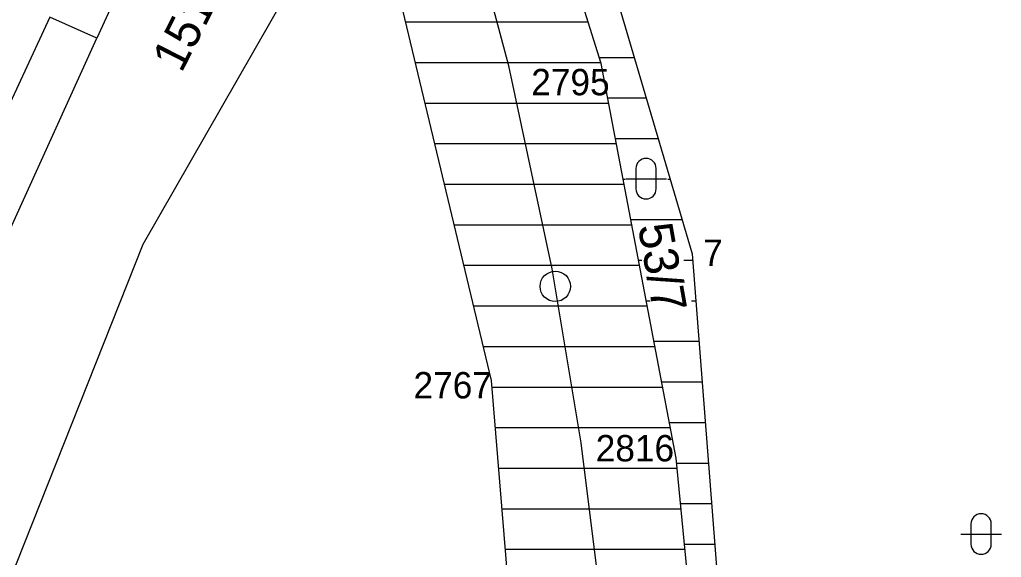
# Model space of a CAD drawing. Extents: x -553916 to -552953, y -1067469 to -1066637.
# Drawn here: x -553532.46 to -553484.03, y -1067025.62 to -1066999.11 of the extents above; entities that cross this region are included whole.
import ezdxf

# ---------------------------------------------------------------- set-up
doc = ezdxf.new("R2010")
doc.units = 0
for name, color, linetype in [('Hranice parcel', 7, 'Continuous'), ('Kolej', 7, 'Continuous'), ('Návěst místo trati', 7, 'Continuous'), ('Parcelní čísla', 7, 'Continuous'), ('Propustek', 7, 'Continuous'), ('Vrstva 1', 7, 'Continuous'), ('Vrstva 60', 7, 'Continuous'), ('Značky kultur', 7, 'Continuous')]:
    doc.layers.add(name, color=color, linetype=linetype)

msp = doc.modelspace()

# ---------------------------------------------------------------- linework, layer by layer
at = {"layer": 'Hranice parcel'}
for p, q in [((-553519.4, -1066979.7), (-553528.66, -1067000.03)), ((-553530.98, -1066998.99), (-553538.9, -1067016.05)), ((-553528.66, -1067000.03), (-553530.98, -1066998.99)), ((-553535.85, -1067015.85), (-553528.66, -1067000.03))]:
    msp.add_line(p, q, dxfattribs=at)
msp.add_lwpolyline([(-553515.43, -1066991.08), (-553526.38, -1067010.19), (-553539.65, -1067043.59), (-553548.33, -1067069.03)], dxfattribs=at)
at = {"layer": 'Kolej'}
msp.add_lwpolyline([(-553503.324, -1067065.808), (-553502.678, -1067054.027), (-553502.762, -1067041.504), (-553503.626, -1067029.057), (-553504.756, -1067019.974), (-553506.183, -1067011.388), (-553508.328, -1067001.388), (-553510.948, -1066991.622), (-553512.921, -1066985.291), (-553515.647, -1066977.347), (-553517.422, -1066972.53), (-553519.157, -1066967.95), (-553522.886, -1066958.375), (-553529.101, -1066942.549), (-553538.686, -1066918.107), (-553542.908, -1066907.329), (-553546.692, -1066897.676), (-553555.025, -1066876.441), (-553564.644, -1066851.894), (-553574.241, -1066827.427), (-553583.19, -1066804.618)], dxfattribs=at)
at = {"layer": 'Návěst místo trati'}
msp.add_circle((-553506.038, -1067012.26), 0.75, dxfattribs=at)
at = {"layer": 'Propustek'}
for p, q in [((-553505.83, -1066988.51), (-553499.28, -1067010.65)), ((-553513.415, -1066999.222), (-553504.415, -1066999.222)), ((-553512.936, -1067001.222), (-553503.788, -1067001.222)), ((-553503.867, -1067000.97), (-553502.144, -1067000.97)), ((-553512.457, -1067003.222), (-553503.402, -1067003.222)), ((-553503.449, -1067002.97), (-553501.552, -1067002.97)), ((-553503.07, -1067004.97), (-553500.96, -1067004.97)), ((-553511.978, -1067005.222), (-553503.022, -1067005.222)), ((-553502.691, -1067006.97), (-553502.584, -1067006.97)), ((-553500.49, -1067006.97), (-553500.369, -1067006.97)), ((-553511.499, -1067007.222), (-553502.643, -1067007.222)), ((-553502.311, -1067008.97), (-553499.777, -1067008.97)), ((-553511.02, -1067009.222), (-553502.263, -1067009.222)), ((-553501.932, -1067010.97), (-553501.762, -1067010.97)), ((-553499.692, -1067010.97), (-553499.255, -1067010.97)), ((-553499.28, -1067010.65), (-553496.78, -1067043.02)), ((-553510.54, -1067011.222), (-553501.884, -1067011.222)), ((-553510.061, -1067013.222), (-553501.504, -1067013.222)), ((-553501.552, -1067012.97), (-553501.355, -1067012.97)), ((-553499.323, -1067012.97), (-553499.101, -1067012.97)), ((-553509.582, -1067015.222), (-553501.125, -1067015.222)), ((-553501.173, -1067014.97), (-553498.946, -1067014.97)), ((-553509.153, -1067017.222), (-553500.746, -1067017.222)), ((-553500.793, -1067016.97), (-553498.792, -1067016.97)), ((-553508.989, -1067019.222), (-553500.366, -1067019.222)), ((-553500.414, -1067018.97), (-553498.637, -1067018.97)), ((-553500.057, -1067020.97), (-553498.483, -1067020.97)), ((-553508.824, -1067021.222), (-553500.032, -1067021.222)), ((-553499.863, -1067022.97), (-553498.329, -1067022.97)), ((-553508.659, -1067023.222), (-553499.838, -1067023.222)), ((-553499.669, -1067024.97), (-553498.174, -1067024.97)), ((-553508.494, -1067025.222), (-553499.644, -1067025.222))]:
    msp.add_line(p, q, dxfattribs=at)
for points in [[(-553498.68, -1067074.42), (-553498.17, -1067040.43), (-553500.08, -1067020.73), (-553503.77, -1067001.28), (-553507.63, -1066988.97), (-553505.83, -1066988.51)], [(-553509.03, -1067072.35), (-553507.22, -1067040.68), (-553509.18, -1067016.9), (-553515.22, -1066991.69), (-553515.43, -1066991.08)]]:
    msp.add_lwpolyline(points, dxfattribs=at)
at = {"layer": 'Vrstva 60'}
for p, q in [((-553503.77, -1067001.28), (-553503.77, -1067001.28)), ((-553499.28, -1067010.65), (-553499.28, -1067010.65)), ((-553509.18, -1067016.9), (-553509.18, -1067016.9)), ((-553500.08, -1067020.73), (-553500.08, -1067020.73))]:
    msp.add_line(p, q, dxfattribs=at)
at = {"layer": 'Značky kultur'}
for p, q in [((-553502.06, -1067006.453), (-553502.06, -1067007.454)), ((-553501.058, -1067007.454), (-553501.058, -1067006.453)), ((-553502.56, -1067006.953), (-553500.558, -1067006.953)), ((-553485.531, -1067023.971), (-553485.531, -1067024.972)), ((-553484.529, -1067024.972), (-553484.529, -1067023.971)), ((-553486.031, -1067024.471), (-553484.029, -1067024.471))]:
    msp.add_line(p, q, dxfattribs=at)
for centre, start, end in [((-553501.559, -1067006.453), 0, 180), ((-553501.559, -1067007.453), 180, 359.9879), ((-553485.03, -1067023.971), 0, 180), ((-553485.03, -1067024.971), 180, 359.9879)]:
    msp.add_arc(centre, 0.5, start, end, dxfattribs=at)

# ---------------------------------------------------------------- texts
at = {"layer": 'Parcelní čísla'}
msp.add_text('1517/7', height=1.7, rotation=63, dxfattribs=at).set_placement((-553524.481, -1067001.782))
at = {"layer": 'Vrstva 1'}
msp.add_text('53/7', height=1.7, rotation=280, dxfattribs=at).set_placement((-553501.965, -1067009.286))
at = {"layer": 'Vrstva 60'}
for s, p in [('2795', (-553507.223, -1067002.841)), ('7', (-553498.742, -1067011.25)), ('2767', (-553513.031, -1067017.784)), ('2816', (-553504.042, -1067020.889))]:
    msp.add_text(s, height=1.3, dxfattribs=at).set_placement(p)

doc.saveas('drawing.dxf')
